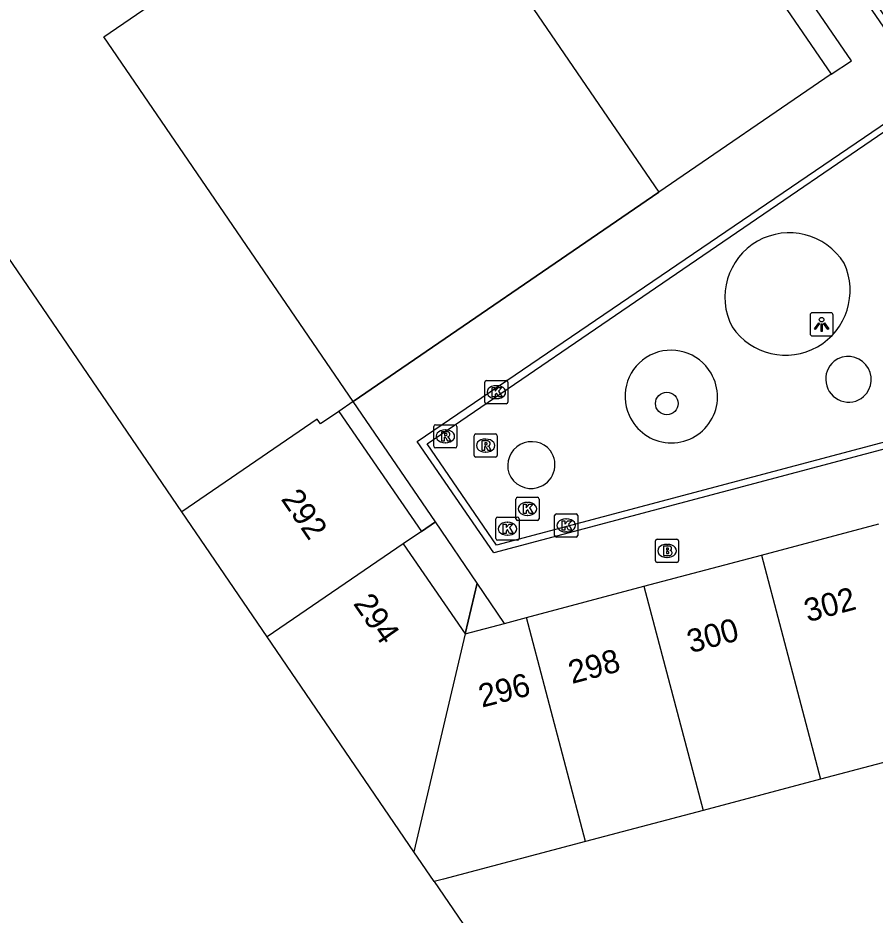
# Model space of a CAD drawing. Extents: x 155275 to 156263, y 382654 to 383635.
# Drawn here: x 155842.67 to 155879.68, y 383114.39 to 383153.11 of the extents above; entities that cross this region are included whole.
import ezdxf

# ---------------------------------------------------------------- set-up
doc = ezdxf.new("R2010")
doc.units = 0
for name, color, linetype in [('IMGEO_Boom', 7, 'Continuous'), ('IMGEO_Brandkraan', 7, 'Continuous'), ('IMGEO_Kolk', 7, 'Continuous'), ('IMGEO_Lichtpunt', 7, 'Continuous'), ('IMGEO_Muur', 7, 'Continuous'), ('IMGEO_Pand', 7, 'Continuous'), ('IMGEO_Pand_nummerreeks', 7, 'Continuous'), ('IMGEO_Pand_overbouw', 7, 'Continuous'), ('IMGEO_Rioolput', 7, 'Continuous'), ('IMGEO_Voetpad_gesloten', 7, 'Continuous'), ('IMGEO_Voetpad_open', 7, 'Continuous')]:
    doc.layers.add(name, color=color, linetype=linetype)

msp = doc.modelspace()

# ---------------------------------------------------------------- linework, layer by layer
at = {"layer": 'IMGEO_Boom'}
msp.add_circle((155870.685, 383136.464), 0.489, dxfattribs=at)
at = {"layer": 'IMGEO_Brandkraan'}
for p, q in [((155870.197, 383129.679), (155870.197, 383130.531)), ((155870.272, 383130.605), (155871.124, 383130.605)), ((155870.685, 383130.385), (155870.71, 383130.385)), ((155871.198, 383130.531), (155871.198, 383129.679)), ((155870.708, 383129.825), (155870.683, 383129.825)), ((155871.124, 383129.605), (155870.272, 383129.605))]:
    msp.add_line(p, q, dxfattribs=at)
for points in [[(155870.197, 383129.679), (155870.197, 383130.531)], [(155870.272, 383130.605), (155871.124, 383130.605)], [(155871.198, 383130.531), (155871.198, 383129.679)], [(155870.545, 383130.305), (155870.545, 383129.905), (155870.758, 383129.905)], [(155870.776, 383130.305), (155870.545, 383130.305)], [(155870.724, 383130.224), (155870.67, 383130.224), (155870.67, 383130.148)], [(155870.67, 383130.148), (155870.723, 383130.148)], [(155870.732, 383130.072), (155870.67, 383130.072), (155870.67, 383129.991)], [(155870.67, 383129.991), (155870.732, 383129.991)], [(155871.124, 383129.605), (155870.272, 383129.605)]]:
    msp.add_lwpolyline(points, dxfattribs=at)
for centre, radius, start, end in [((155870.274, 383130.529), 0.0765, 91.552, 178.448), ((155870.274, 383130.529), 0.0765, 91.552, 178.448), ((155871.122, 383130.529), 0.0765, 1.552, 88.448), ((155871.122, 383130.529), 0.0765, 1.552, 88.448), ((155870.725, 383130.186), 0.0379, 267.8285, 90.9355), ((155870.733, 383130.031), 0.0404, 269.8759, 90.5077), ((155870.78, 383130.16), 0.145, 59.4692, 91.5367), ((155870.805, 383130.207), 0.0922, 285.5137, 58.1501), ((155870.81, 383130.015), 0.105, 301.3115, 78.989), ((155870.274, 383129.681), 0.0765, 181.552, 268.448), ((155870.274, 383129.681), 0.0765, 181.552, 268.448), ((155870.764, 383130.156), 0.251, 268.6676, 293.5347), ((155871.122, 383129.681), 0.0765, 271.552, 358.448), ((155871.122, 383129.681), 0.0765, 271.552, 358.448)]:
    msp.add_arc(centre, radius, start, end, dxfattribs=at)
for centre, major_axis, ratio, start_param, end_param in [((155870.684, 383130.105), (-0.387, 0.002), 0.722429, 4.712389, 7.853982), ((155870.709, 383130.105), (-0.39, 0.002), 0.717154, 1.570796, 4.712389)]:
    msp.add_ellipse(centre, major_axis=major_axis, ratio=ratio, start_param=start_param, end_param=end_param, dxfattribs=at)
at = {"layer": 'IMGEO_Kolk'}
for p, q in [((155862.825, 383136.528), (155862.825, 383137.38)), ((155862.9, 383137.454), (155863.752, 383137.454)), ((155863.826, 383137.38), (155863.826, 383136.528)), ((155863.313, 383137.234), (155863.338, 383137.234)), ((155863.336, 383136.674), (155863.311, 383136.674)), ((155863.752, 383136.454), (155862.9, 383136.454)), ((155864.171, 383131.491), (155864.171, 383132.343)), ((155864.246, 383132.417), (155865.098, 383132.417)), ((155865.172, 383132.343), (155865.172, 383131.491)), ((155864.659, 383132.197), (155864.684, 383132.197)), ((155863.378, 383131.56), (155864.23, 383131.56)), ((155864.682, 383131.637), (155864.657, 383131.637)), ((155865.843, 383130.775), (155865.843, 383131.627)), ((155865.918, 383131.701), (155866.77, 383131.701)), ((155866.844, 383131.627), (155866.844, 383130.775)), ((155863.303, 383130.634), (155863.303, 383131.486)), ((155863.791, 383131.34), (155863.816, 383131.34)), ((155865.098, 383131.417), (155864.246, 383131.417)), ((155864.304, 383131.486), (155864.304, 383130.634)), ((155866.331, 383131.481), (155866.356, 383131.481)), ((155863.814, 383130.78), (155863.789, 383130.78)), ((155866.354, 383130.921), (155866.329, 383130.921)), ((155864.23, 383130.56), (155863.378, 383130.56)), ((155866.77, 383130.701), (155865.918, 383130.701))]:
    msp.add_line(p, q, dxfattribs=at)
for points in [[(155862.825, 383136.528), (155862.825, 383137.38)], [(155862.9, 383137.454), (155863.752, 383137.454)], [(155863.826, 383137.38), (155863.826, 383136.528)], [(155863.146, 383137.154), (155863.269, 383137.154), (155863.269, 383137.003), (155863.399, 383137.154), (155863.563, 383137.154), (155863.417, 383137.003), (155863.57, 383136.754), (155863.418, 383136.754), (155863.333, 383136.918), (155863.269, 383136.851), (155863.269, 383136.754), (155863.146, 383136.754), (155863.146, 383137.154)], [(155863.752, 383136.454), (155862.9, 383136.454)], [(155864.171, 383131.491), (155864.171, 383132.343)], [(155864.246, 383132.417), (155865.098, 383132.417)], [(155865.172, 383132.343), (155865.172, 383131.491)], [(155864.492, 383132.117), (155864.615, 383132.117), (155864.615, 383131.966), (155864.745, 383132.117), (155864.909, 383132.117), (155864.763, 383131.966), (155864.916, 383131.717), (155864.764, 383131.717), (155864.679, 383131.881), (155864.615, 383131.814), (155864.615, 383131.717), (155864.492, 383131.717), (155864.492, 383132.117)], [(155863.378, 383131.56), (155864.23, 383131.56)], [(155865.843, 383130.775), (155865.843, 383131.627)], [(155865.918, 383131.701), (155866.77, 383131.701)], [(155866.844, 383131.627), (155866.844, 383130.775)], [(155863.303, 383130.634), (155863.303, 383131.486)], [(155863.624, 383131.26), (155863.747, 383131.26), (155863.747, 383131.109), (155863.877, 383131.26), (155864.041, 383131.26), (155863.895, 383131.109), (155864.048, 383130.86), (155863.896, 383130.86), (155863.811, 383131.024), (155863.747, 383130.957), (155863.747, 383130.86), (155863.624, 383130.86), (155863.624, 383131.26)], [(155865.098, 383131.417), (155864.246, 383131.417)], [(155864.304, 383131.486), (155864.304, 383130.634)], [(155866.164, 383131.401), (155866.287, 383131.401), (155866.287, 383131.25), (155866.417, 383131.401), (155866.581, 383131.401), (155866.435, 383131.25), (155866.588, 383131.001), (155866.436, 383131.001), (155866.351, 383131.165), (155866.287, 383131.098), (155866.287, 383131.001), (155866.164, 383131.001), (155866.164, 383131.401)], [(155864.23, 383130.56), (155863.378, 383130.56)], [(155866.77, 383130.701), (155865.918, 383130.701)]]:
    msp.add_lwpolyline(points, dxfattribs=at)
for centre, start, end in [((155862.902, 383137.378), 91.552, 178.448), ((155862.902, 383137.378), 91.552, 178.448), ((155863.75, 383137.378), 1.552, 88.448), ((155863.75, 383137.378), 1.552, 88.448), ((155862.902, 383136.53), 181.552, 268.448), ((155862.902, 383136.53), 181.552, 268.448), ((155863.75, 383136.53), 271.552, 358.448), ((155863.75, 383136.53), 271.552, 358.448), ((155864.248, 383132.341), 91.552, 178.448), ((155864.248, 383132.341), 91.552, 178.448), ((155865.096, 383132.341), 1.552, 88.448), ((155865.096, 383132.341), 1.552, 88.448), ((155863.38, 383131.484), 91.552, 178.448), ((155863.38, 383131.484), 91.552, 178.448), ((155864.228, 383131.484), 1.552, 88.448), ((155864.228, 383131.484), 1.552, 88.448), ((155865.92, 383131.625), 91.552, 178.448), ((155865.92, 383131.625), 91.552, 178.448), ((155866.768, 383131.625), 1.552, 88.448), ((155866.768, 383131.625), 1.552, 88.448), ((155864.248, 383131.493), 181.552, 268.448), ((155864.248, 383131.493), 181.552, 268.448), ((155865.096, 383131.493), 271.552, 358.448), ((155865.096, 383131.493), 271.552, 358.448), ((155865.92, 383130.777), 181.552, 268.448), ((155865.92, 383130.777), 181.552, 268.448), ((155866.768, 383130.777), 271.552, 358.448), ((155866.768, 383130.777), 271.552, 358.448), ((155863.38, 383130.636), 181.552, 268.448), ((155863.38, 383130.636), 181.552, 268.448), ((155864.228, 383130.636), 271.552, 358.448), ((155864.228, 383130.636), 271.552, 358.448)]:
    msp.add_arc(centre, 0.0765, start, end, dxfattribs=at)
for centre, major_axis, ratio, start_param, end_param in [((155863.312, 383136.954), (-0.387, 0.002), 0.722429, 4.712389, 7.853982), ((155863.337, 383136.954), (-0.39, 0.002), 0.717154, 1.570796, 4.712389), ((155864.658, 383131.917), (-0.387, 0.002), 0.722429, 4.712389, 7.853982), ((155864.683, 383131.917), (-0.39, 0.002), 0.717154, 1.570796, 4.712389), ((155863.79, 383131.06), (-0.387, 0.002), 0.722429, 4.712389, 7.853982), ((155863.815, 383131.06), (-0.39, 0.002), 0.717154, 1.570796, 4.712389), ((155866.33, 383131.201), (-0.387, 0.002), 0.722429, 4.712389, 7.853982), ((155866.355, 383131.201), (-0.39, 0.002), 0.717154, 1.570796, 4.712389)]:
    msp.add_ellipse(centre, major_axis=major_axis, ratio=ratio, start_param=start_param, end_param=end_param, dxfattribs=at)
at = {"layer": 'IMGEO_Lichtpunt'}
for p, q in [((155876.873, 383140.285), (155876.873, 383139.478)), ((155876.873, 383140.285), (155876.873, 383139.478)), ((155877.775, 383140.38), (155876.967, 383140.38)), ((155877.775, 383140.38), (155876.967, 383140.38)), ((155877.869, 383139.478), (155877.869, 383140.285)), ((155877.869, 383139.478), (155877.869, 383140.285)), ((155876.967, 383139.384), (155877.775, 383139.384)), ((155876.967, 383139.384), (155877.775, 383139.384))]:
    msp.add_line(p, q, dxfattribs=at)
for points in [[(155877.247, 383139.949), (155877.286, 383139.921), (155877.098, 383139.659), (155877.06, 383139.686), (155877.247, 383139.949)], [(155877.349, 383139.901), (155877.396, 383139.901), (155877.396, 383139.579), (155877.349, 383139.579), (155877.349, 383139.901)], [(155877.459, 383139.921), (155877.497, 383139.948), (155877.684, 383139.686), (155877.645, 383139.658), (155877.459, 383139.921)]]:
    msp.add_lwpolyline(points, dxfattribs=at)
msp.add_circle((155877.372, 383140.083), 0.0994, dxfattribs=at)
for centre, start, end in [((155876.967, 383140.285), 90, 180), ((155876.967, 383140.285), 90, 180), ((155877.775, 383140.285), 0, 90), ((155877.775, 383140.285), 0, 90), ((155876.967, 383139.478), 180, 270), ((155876.967, 383139.478), 180, 270), ((155877.775, 383139.478), 270, 0), ((155877.775, 383139.478), 270, 360)]:
    msp.add_arc(centre, 0.0946, start, end, dxfattribs=at)
at = {"layer": 'IMGEO_Muur'}
msp.add_lwpolyline([(155857.147, 383136.552), (155870.344, 383145.585)], dxfattribs=at)
at = {"layer": 'IMGEO_Pand'}
for points in [[(155856.897, 383181.221), (155870.168, 383161.81), (155873.417, 383157.058), (155877.781, 383150.676), (155870.344, 383145.585)], [(155857.147, 383136.552), (155846.372, 383152.299), (155859.58, 383161.33), (155870.344, 383145.585)], [(155849.738, 383131.795), (155838.796, 383147.806)], [(155857.147, 383136.552), (155856.519, 383136.122)], [(155856.519, 383136.122), (155855.731, 383135.583), (155855.586, 383135.793), (155849.738, 383131.795)], [(155856.519, 383136.122), (155860.095, 383130.941), (155859.307, 383130.402)], [(155853.434, 383126.387), (155849.738, 383131.795)], [(155874.772, 383129.925), (155879.846, 383131.275)], [(155859.307, 383130.402), (155853.434, 383126.387)], [(155859.307, 383130.402), (155861.985, 383126.523)], [(155869.699, 383128.575), (155874.772, 383129.925)], [(155874.772, 383129.925), (155877.326, 383120.249)], [(155864.626, 383127.224), (155869.699, 383128.575)], [(155869.699, 383128.575), (155872.251, 383118.905)], [(155861.985, 383126.523), (155863.68, 383126.972), (155864.626, 383127.224)], [(155867.176, 383117.561), (155864.626, 383127.224)], [(155861.985, 383126.523), (155859.767, 383117.12)], [(155859.767, 383117.12), (155853.434, 383126.387)], [(155882.401, 383121.593), (155877.326, 383120.249)], [(155877.326, 383120.249), (155872.251, 383118.905)], [(155872.251, 383118.905), (155867.176, 383117.561)], [(155867.176, 383117.561), (155861.037, 383115.935), (155860.647, 383115.831)], [(155860.647, 383115.831), (155859.767, 383117.12)], [(155860.647, 383115.831), (155864.977, 383109.495), (155862.029, 383101.349), (155862.607, 383100.608)]]:
    msp.add_lwpolyline(points, dxfattribs=at)
at = {"layer": 'IMGEO_Pand_overbouw'}
for points in [[(155858.008, 383181.485), (155856.897, 383181.221), (155870.168, 383161.81), (155873.417, 383157.058), (155877.781, 383150.676), (155878.659, 383151.254), (155874.289, 383157.65), (155871.046, 383162.398)], [(155857.147, 383136.552), (155856.519, 383136.122), (155860.095, 383130.941), (155860.694, 383131.351)], [(155860.694, 383131.351), (155860.095, 383130.941), (155859.307, 383130.402), (155861.985, 383126.523), (155862.5, 383128.704)], [(155861.985, 383126.523), (155863.68, 383126.972), (155862.5, 383128.704)]]:
    msp.add_lwpolyline(points, close=True, dxfattribs=at)
at = {"layer": 'IMGEO_Rioolput'}
for p, q in [((155860.623, 383134.623), (155860.623, 383135.475)), ((155860.698, 383135.549), (155861.55, 383135.549)), ((155861.624, 383135.475), (155861.624, 383134.623)), ((155861.111, 383135.329), (155861.136, 383135.329)), ((155862.363, 383134.223), (155862.363, 383135.075)), ((155862.438, 383135.149), (155863.29, 383135.149)), ((155863.364, 383135.075), (155863.364, 383134.223)), ((155861.134, 383134.769), (155861.109, 383134.769)), ((155862.851, 383134.929), (155862.876, 383134.929)), ((155861.55, 383134.549), (155860.698, 383134.549)), ((155862.874, 383134.369), (155862.849, 383134.369)), ((155863.29, 383134.149), (155862.438, 383134.149))]:
    msp.add_line(p, q, dxfattribs=at)
for points in [[(155860.623, 383134.623), (155860.623, 383135.475)], [(155860.698, 383135.549), (155861.55, 383135.549)], [(155861.624, 383135.475), (155861.624, 383134.623)], [(155861.212, 383135.247), (155860.96, 383135.249), (155860.96, 383134.849)], [(155861.138, 383135.168), (155861.084, 383135.168), (155861.084, 383135.087)], [(155861.084, 383135.087), (155861.136, 383135.087)], [(155862.363, 383134.223), (155862.363, 383135.075)], [(155862.438, 383135.149), (155863.29, 383135.149)], [(155863.364, 383135.075), (155863.364, 383134.223)], [(155860.96, 383134.849), (155861.084, 383134.849), (155861.084, 383135.011), (155861.095, 383135.011)], [(155861.142, 383134.982), (155861.213, 383134.849), (155861.353, 383134.849), (155861.288, 383134.975)], [(155862.952, 383134.847), (155862.7, 383134.849), (155862.7, 383134.449)], [(155862.878, 383134.768), (155862.824, 383134.768), (155862.824, 383134.687)], [(155862.824, 383134.687), (155862.876, 383134.687)], [(155861.55, 383134.549), (155860.698, 383134.549)], [(155862.7, 383134.449), (155862.824, 383134.449), (155862.824, 383134.611), (155862.835, 383134.611)], [(155862.882, 383134.582), (155862.953, 383134.449), (155863.093, 383134.449), (155863.028, 383134.575)], [(155863.29, 383134.149), (155862.438, 383134.149)]]:
    msp.add_lwpolyline(points, dxfattribs=at)
for centre, radius, start, end in [((155860.7, 383135.473), 0.0765, 91.552, 178.448), ((155860.7, 383135.473), 0.0765, 91.552, 178.448), ((155861.548, 383135.473), 0.0765, 1.552, 88.448), ((155861.548, 383135.473), 0.0765, 1.552, 88.448), ((155861.12, 383135.276), 0.19, 274.7715, 282.9687), ((155861.144, 383135.072), 0.0964, 77.0061, 93.1865), ((155861.158, 383135.129), 0.0378, 276.6634, 79.6772), ((155861.211, 383135.137), 0.109, 350.3612, 89.416), ((155861.209, 383135.137), 0.112, 277.5842, 350.9817), ((155862.44, 383135.073), 0.0765, 91.552, 178.448), ((155862.44, 383135.073), 0.0765, 91.552, 178.448), ((155863.288, 383135.073), 0.0765, 1.552, 88.448), ((155863.288, 383135.073), 0.0765, 1.552, 88.448), ((155861.094, 383134.958), 0.0533, 26.0293, 88.6989), ((155861.193, 383134.922), 0.108, 29.5134, 73.7905), ((155862.86, 383134.876), 0.19, 274.7715, 282.9687), ((155862.884, 383134.672), 0.0964, 77.0061, 93.1865), ((155862.898, 383134.729), 0.0378, 276.6634, 79.6772), ((155862.951, 383134.737), 0.109, 350.3612, 89.416), ((155862.949, 383134.737), 0.112, 277.5842, 350.9817), ((155860.7, 383134.625), 0.0765, 181.552, 268.448), ((155860.7, 383134.625), 0.0765, 181.552, 268.448), ((155861.548, 383134.625), 0.0765, 271.552, 358.448), ((155861.548, 383134.625), 0.0765, 271.552, 358.448), ((155862.834, 383134.558), 0.0533, 26.0293, 88.6989), ((155862.933, 383134.522), 0.108, 29.5134, 73.7905), ((155862.44, 383134.225), 0.0765, 181.552, 268.448), ((155862.44, 383134.225), 0.0765, 181.552, 268.448), ((155863.288, 383134.225), 0.0765, 271.552, 358.448), ((155863.288, 383134.225), 0.0765, 271.552, 358.448)]:
    msp.add_arc(centre, radius, start, end, dxfattribs=at)
for centre, major_axis, ratio, start_param, end_param in [((155861.11, 383135.049), (-0.387, 0.002), 0.722429, 4.712389, 7.853982), ((155861.135, 383135.049), (-0.39, 0.002), 0.717154, 1.570796, 4.712389), ((155862.85, 383134.649), (-0.387, 0.002), 0.722429, 4.712389, 7.853982), ((155862.875, 383134.649), (-0.39, 0.002), 0.717154, 1.570796, 4.712389)]:
    msp.add_ellipse(centre, major_axis=major_axis, ratio=ratio, start_param=start_param, end_param=end_param, dxfattribs=at)
at = {"layer": 'IMGEO_Voetpad_gesloten'}
for points in [[(155902.448, 383191.426), (155931.963, 383148.284), (155863.219, 383130.024), (155859.907, 383134.822), (155882.014, 383149.858), (155875.989, 383158.653), (155876.216, 383158.871)], [(155902.172, 383191.367), (155931.5, 383148.452), (155863.327, 383130.346), (155860.338, 383134.727), (155882.417, 383149.798), (155876.216, 383158.871)]]:
    msp.add_lwpolyline(points, dxfattribs=at)
at = {"layer": 'IMGEO_Voetpad_open'}
msp.add_lwpolyline([(155870.344, 383145.585), (155857.147, 383136.552)], dxfattribs=at)
for centre, radius, start, end in [((155875.978, 383141.052), 2.783, 31.954, 207.39), ((155875.814, 383141.34), 2.789, 214.2119, 25.1322), ((155870.873, 383136.78), 1.987, 29.9021, 204.4414), ((155878.544, 383137.52), 0.995, 129.5424, 310.3047), ((155878.519, 383137.499), 0.996, 312.1831, 127.664), ((155870.887, 383136.754), 1.989, 203.5957, 30.7478), ((155864.851, 383133.78), 1.037, 38.6007, 198.172), ((155864.827, 383133.825), 1.029, 285.7484, 35.8126), ((155864.827, 383133.826), 1.029, 200.999, 285.7231)]:
    msp.add_arc(centre, radius, start, end, dxfattribs=at)

# ---------------------------------------------------------------- texts
at = {"layer": 'IMGEO_Pand_nummerreeks'}
for s, rotation, p in [('292', 304.446, (155853.998, 383132.342)), ('302', 15.1509, (155876.776, 383127.018)), ('294', 304.8101, (155857.119, 383127.826)), ('300', 15.0039, (155871.715, 383125.683)), ('298', 14.8684, (155866.592, 383124.357)), ('296', 14.262, (155862.702, 383123.335))]:
    msp.add_text(s, height=1, rotation=rotation, dxfattribs=at).set_placement(p)

doc.saveas('drawing.dxf')
